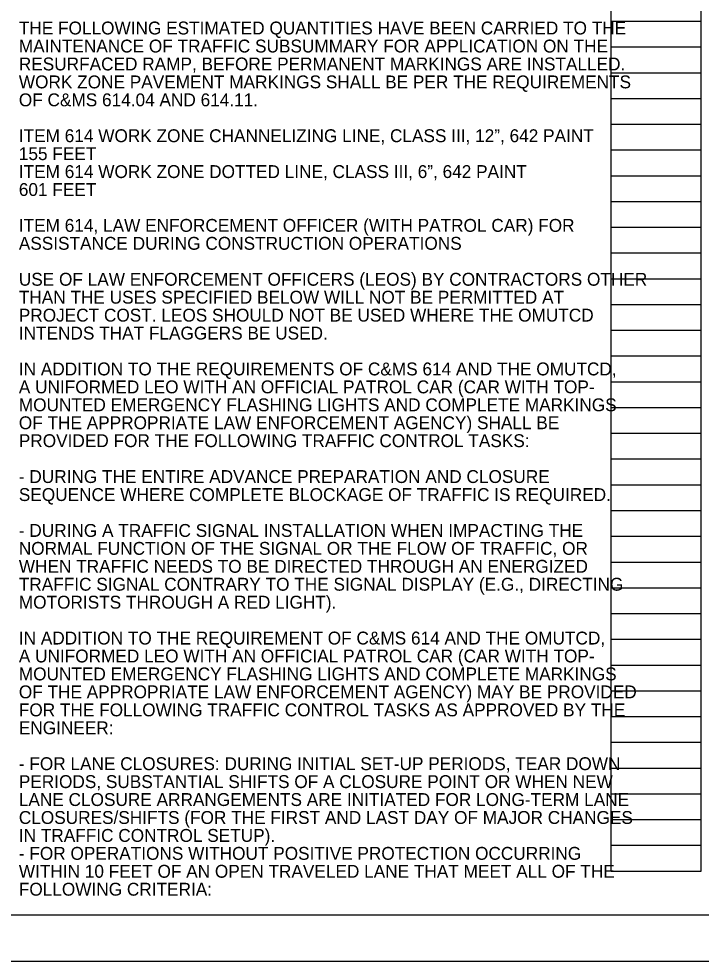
# Model space of a CAD drawing. Extents: x 0 to 34, y 0 to 22.
# Drawn here: x 17.24 to 24.66, y 0 to 10.25 of the extents above; entities that cross this region are included whole.
import ezdxf

# ---------------------------------------------------------------- set-up
doc = ezdxf.new("R2010")
doc.units = 0
for name, color, linetype in [('SH_Border', 7, 'Continuous'), ('SH_Cut_Line', 7, 'Continuous'), ('SH_Data', 7, 'Continuous'), ('SH_Text', 7, 'Continuous')]:
    doc.layers.add(name, color=color, linetype=linetype)

msp = doc.modelspace()

# ---------------------------------------------------------------- linework, layer by layer
at = {"layer": 'SH_Border'}
msp.add_lwpolyline([(1.5, 21.5), (33.5, 21.5), (33.5, 0.5), (1.5, 0.5)], close=True, dxfattribs=at)
at = {"layer": 'SH_Cut_Line'}
msp.add_lwpolyline([(0, 0), (34, 0), (34, 22), (0, 22)], close=True, dxfattribs=at)
at = {"layer": 'SH_Data'}
for p, q in [((23.68, 0.98), (23.68, 21.14)), ((24.66, 0.98), (24.66, 21.14)), ((23.68, 10.22), (24.66, 10.22)), ((23.68, 9.94), (24.66, 9.94)), ((23.68, 9.66), (24.66, 9.66)), ((23.68, 9.38), (24.66, 9.38)), ((23.68, 9.1), (24.66, 9.1)), ((23.68, 8.82), (24.66, 8.82)), ((23.68, 8.54), (24.66, 8.54)), ((23.68, 8.26), (24.66, 8.26)), ((23.68, 7.98), (24.66, 7.98)), ((23.68, 7.7), (24.66, 7.7)), ((23.68, 7.42), (24.66, 7.42)), ((23.68, 7.14), (24.66, 7.14)), ((23.68, 6.86), (24.66, 6.86)), ((23.68, 6.58), (24.66, 6.58)), ((23.68, 6.3), (24.66, 6.3)), ((23.68, 6.02), (24.66, 6.02)), ((23.68, 5.74), (24.66, 5.74)), ((23.68, 5.46), (24.66, 5.46)), ((23.68, 5.18), (24.66, 5.18)), ((23.68, 4.9), (24.66, 4.9)), ((23.68, 4.62), (24.66, 4.62)), ((23.68, 4.34), (24.66, 4.34)), ((23.68, 4.06), (24.66, 4.06)), ((23.68, 3.78), (24.66, 3.78)), ((23.68, 3.5), (24.66, 3.5)), ((23.68, 3.22), (24.66, 3.22)), ((23.68, 2.94), (24.66, 2.94)), ((23.68, 2.66), (24.66, 2.66)), ((23.68, 2.38), (24.66, 2.38)), ((23.68, 2.1), (24.66, 2.1)), ((23.68, 1.82), (24.66, 1.82)), ((23.68, 1.54), (24.66, 1.54)), ((23.68, 1.26), (24.66, 1.26)), ((23.68, 0.98), (24.66, 0.98))]:
    msp.add_line(p, q, dxfattribs=at)

# ---------------------------------------------------------------- texts
at = {"layer": 'SH_Text'}
for s, p in [('THE FOLLOWING ESTIMATED QUANTITIES HAVE BEEN CARRIED TO THE ', (17.24, 10.076)), ('MAINTENANCE OF TRAFFIC SUBSUMMARY FOR APPLICATION ON THE ', (17.24, 9.88)), ('RESURFACED RAMP, BEFORE PERMANENT MARKINGS ARE INSTALLED. ', (17.24, 9.685)), ('WORK ZONE PAVEMENT MARKINGS SHALL BE PER THE REQUIREMENTS ', (17.24, 9.49)), ('OF C&MS 614.04 AND 614.11. ', (17.24, 9.295)), ('ITEM 614 WORK ZONE CHANNELIZING LINE, CLASS III, 12”, 642 PAINT', (17.24, 8.905)), ('155 FEET', (17.24, 8.71)), ('ITEM 614 WORK ZONE DOTTED LINE, CLASS III, 6”, 642 PAINT', (17.24, 8.515)), ('601 FEET', (17.24, 8.32)), ('ITEM 614, LAW ENFORCEMENT OFFICER (WITH PATROL CAR) FOR ', (17.24, 7.93)), ('ASSISTANCE DURING CONSTRUCTION OPERATIONS ', (17.24, 7.735)), ('USE OF LAW ENFORCEMENT OFFICERS (LEOS) BY CONTRACTORS OTHER ', (17.24, 7.344)), ('THAN THE USES SPECIFIED BELOW WILL NOT BE PERMITTED AT ', (17.24, 7.149)), ('PROJECT COST. LEOS SHOULD NOT BE USED WHERE THE OMUTCD ', (17.24, 6.954)), ('INTENDS THAT FLAGGERS BE USED.', (17.24, 6.759)), ('IN ADDITION TO THE REQUIREMENTS OF C&MS 614 AND THE OMUTCD, ', (17.24, 6.369)), ('A UNIFORMED LEO WITH AN OFFICIAL PATROL CAR (CAR WITH TOP-', (17.24, 6.174)), ('MOUNTED EMERGENCY FLASHING LIGHTS AND COMPLETE MARKINGS ', (17.24, 5.979)), ('OF THE APPROPRIATE LAW ENFORCEMENT AGENCY) SHALL BE ', (17.24, 5.784)), ('PROVIDED FOR THE FOLLOWING TRAFFIC CONTROL TASKS: ', (17.24, 5.589)), ('- DURING THE ENTIRE ADVANCE PREPARATION AND CLOSURE ', (17.24, 5.199)), ('SEQUENCE WHERE COMPLETE BLOCKAGE OF TRAFFIC IS REQUIRED. ', (17.24, 5.003)), ('- DURING A TRAFFIC SIGNAL INSTALLATION WHEN IMPACTING THE ', (17.24, 4.613)), ('NORMAL FUNCTION OF THE SIGNAL OR THE FLOW OF TRAFFIC, OR ', (17.24, 4.418)), ('WHEN TRAFFIC NEEDS TO BE DIRECTED THROUGH AN ENERGIZED ', (17.24, 4.223)), ('TRAFFIC SIGNAL CONTRARY TO THE SIGNAL DISPLAY (E.G., DIRECTING ', (17.24, 4.028)), ('MOTORISTS THROUGH A RED LIGHT).', (17.24, 3.833)), ('IN ADDITION TO THE REQUIREMENT OF C&MS 614 AND THE OMUTCD, ', (17.24, 3.443)), ('A UNIFORMED LEO WITH AN OFFICIAL PATROL CAR (CAR WITH TOP-', (17.24, 3.248)), ('MOUNTED EMERGENCY FLASHING LIGHTS AND COMPLETE MARKINGS ', (17.24, 3.053)), ('OF THE APPROPRIATE LAW ENFORCEMENT AGENCY) MAY BE PROVIDED ', (17.24, 2.858)), ('FOR THE FOLLOWING TRAFFIC CONTROL TASKS AS APPROVED BY THE ', (17.24, 2.662)), ('ENGINEER:', (17.24, 2.467)), ('- FOR LANE CLOSURES: DURING INITIAL SET-UP PERIODS, TEAR DOWN ', (17.24, 2.077)), ('PERIODS, SUBSTANTIAL SHIFTS OF A CLOSURE POINT OR WHEN NEW ', (17.24, 1.882)), ('LANE CLOSURE ARRANGEMENTS ARE INITIATED FOR LONG-TERM LANE ', (17.24, 1.687)), ('CLOSURES/SHIFTS (FOR THE FIRST AND LAST DAY OF MAJOR CHANGES ', (17.24, 1.492)), ('IN TRAFFIC CONTROL SETUP). ', (17.24, 1.297)), ('- FOR OPERATIONS WITHOUT POSITIVE PROTECTION OCCURRING ', (17.24, 1.102)), ('WITHIN 10 FEET OF AN OPEN TRAVELED LANE THAT MEET ALL OF THE ', (17.24, 0.907)), ('FOLLOWING CRITERIA: ', (17.24, 0.712))]:
    msp.add_text(s, height=0.14, dxfattribs=at).set_placement(p)

doc.saveas('drawing.dxf')
